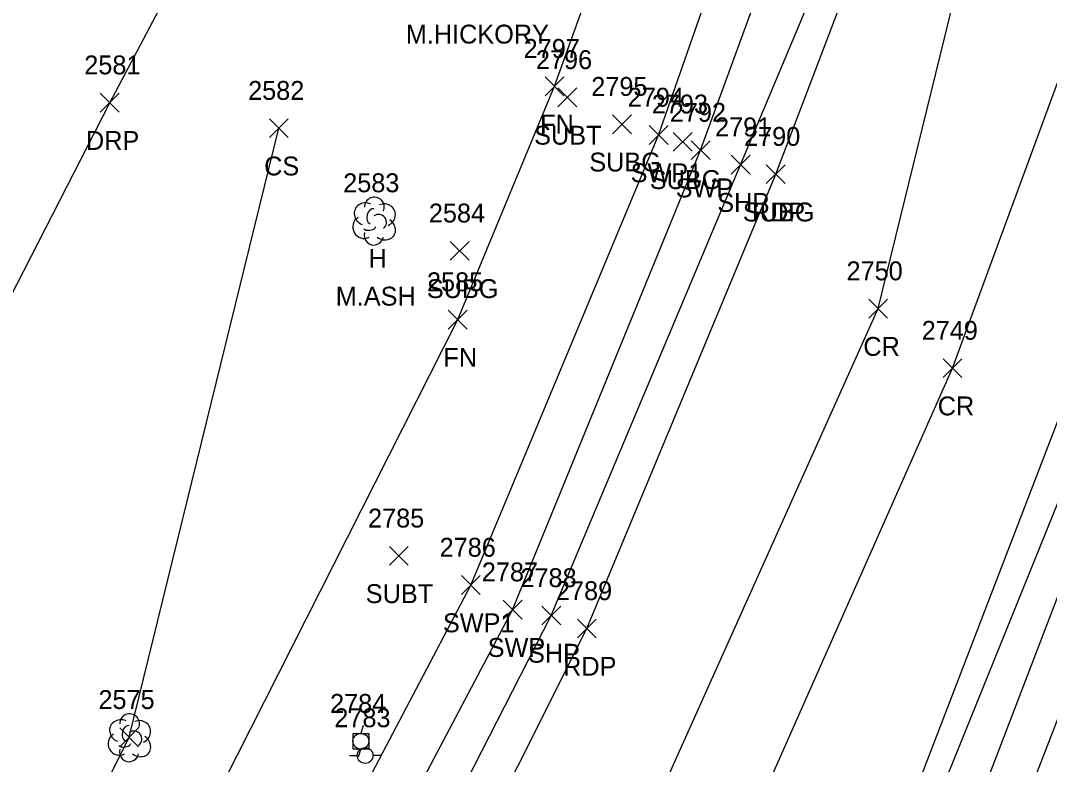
# Model space of a CAD drawing. Extents: x 1477930 to 1480780, y 774090 to 784647.
# Drawn here: x 1479402.4 to 1479511.3, y 774963.7 to 775042.4 of the extents above; entities that cross this region are included whole.
import ezdxf

# ---------------------------------------------------------------- set-up
doc = ezdxf.new("R2010")
doc.units = 0
for name, color, linetype in [('L_A', 7, 'Continuous'), ('L_C', 7, 'Continuous'), ('L_I', 7, 'Continuous'), ('L_TIC', 7, 'Continuous'), ('LELB', 7, 'Continuous'), ('LFNC', 7, 'Continuous'), ('LTD', 7, 'Continuous'), ('P_A', 7, 'Continuous'), ('P_I', 7, 'Continuous'), ('P_TIC', 7, 'Continuous'), ('PET', 7, 'Continuous'), ('PRC', 7, 'Continuous'), ('PSP', 7, 'Continuous'), ('R_A', 7, 'Continuous'), ('R_I', 7, 'Continuous'), ('R_TIC', 7, 'Continuous'), ('RDP', 7, 'Continuous'), ('RSW', 7, 'Continuous'), ('U_A', 7, 'Continuous'), ('U_I', 7, 'Continuous'), ('U_TIC', 7, 'Continuous'), ('UP', 7, 'Continuous')]:
    doc.layers.add(name, color=color, linetype=linetype)

msp = doc.modelspace()

# ---------------------------------------------------------------- linework, layer by layer
at = {"layer": 'L_TIC'}
for points in [[(1479457.93, 775034.46), (1479459.93, 775036.46)], [(1479459.93, 775034.46), (1479457.93, 775036.46)], [(1479428.74, 775030.02), (1479430.74, 775032.02)], [(1479430.74, 775030.02), (1479428.74, 775032.02)], [(1479447.69, 775009.76), (1479449.69, 775011.76)], [(1479449.69, 775009.76), (1479447.69, 775011.76)], [(1479412.9, 774965.54), (1479414.9, 774967.54)], [(1479414.9, 774965.54), (1479412.9, 774967.54)]]:
    msp.add_lwpolyline(points, dxfattribs=at)
at = {"layer": 'LELB'}
for points in [[(1479495.75, 774910.51), (1479499.97, 774927.51), (1479504.38, 774948.16), (1479520.64, 774990.18), (1479525.58, 774996.15), (1479529.8, 774996.91), (1479531.37, 775007.34), (1479547.96, 775049.91), (1479566.92, 775099.68), (1479572.67, 775121.86), (1479581.47, 775151.49), (1479585.92, 775173.63), (1479582, 775184.73)], [(1479486.95, 774912.8), (1479492.72, 774931.11), (1479499.77, 774948.95), (1479521.2, 775004.85), (1479538.58, 775052.83), (1479555.32, 775104.12), (1479560.27, 775119.97)], [(1479384.48, 774907.4), (1479413.9, 774966.54), (1479429.74, 775031.02)]]:
    msp.add_lwpolyline(points, dxfattribs=at)
at = {"layer": 'LFNC'}
msp.add_lwpolyline([(1479373.09, 774875.08), (1479392.41, 774904.48), (1479409.31, 774932.95), (1479448.69, 775010.76), (1479458.93, 775035.46), (1479472.64, 775073.43), (1479490.33, 775128.57)], dxfattribs=at)
at = {"layer": 'LTD'}
for p, q in [((1479439.82, 775021.24), (1479439.82, 775021.24)), ((1479439.82, 775021.24), (1479439.82, 775021.24)), ((1479413.9, 774966.54), (1479413.9, 774966.54)), ((1479413.9, 774966.54), (1479413.9, 774966.54))]:
    msp.add_line(p, q, dxfattribs=at)
for centre in [(1479439.86, 775022.67), (1479413.94, 774967.97)]:
    msp.add_arc(centre, 1.05, 335.5272, 180.9563, dxfattribs=at)
for centre, major_axis, ratio, start_param, end_param in [((1479439.02, 775021.91), (1.21, -0.51), 0.895232, 1.570796, 4.712389), ((1479439.61, 775021.7), (-0.208, -0.792), 0.645439, 3.141593, 6.283185), ((1479440.86, 775021.82), (-1.14, -0.48), 0.949671, 1.570796, 4.712389), ((1479438.73, 775020.53), (0.58, -1.04), 0.959034, 3.141593, 6.283185), ((1479440.32, 775021.07), (-0.5, 0.667), 0.989748, 3.141593, 6.283185), ((1479440.82, 775020.41), (-1.09, 0.79), 0.841452, 1.570796, 4.712389), ((1479439.36, 775020.49), (-0.625, -0.083), 0.423636, 0, 3.141593), ((1479439.82, 775019.74), (0.26, 1.06), 0.942809, 1.570796, 4.712389), ((1479413.11, 774967.2), (1.21, -0.51), 0.895232, 1.570796, 4.712389), ((1479413.69, 774966.99), (-0.208, -0.792), 0.645439, 3.141593, 6.283185), ((1479414.94, 774967.12), (-1.14, -0.48), 0.949671, 1.570796, 4.712389), ((1479412.81, 774965.83), (0.58, -1.04), 0.959034, 3.141593, 6.283185), ((1479414.4, 774966.37), (-0.5, 0.667), 0.989748, 3.141593, 6.283185), ((1479413.44, 774965.79), (-0.625, -0.083), 0.423636, 0, 3.141593), ((1479414.9, 774965.7), (-1.09, 0.79), 0.841452, 1.570796, 4.712389), ((1479413.9, 774965.04), (0.26, 1.06), 0.942809, 1.570796, 4.712389)]:
    msp.add_ellipse(centre, major_axis=major_axis, ratio=ratio, start_param=start_param, end_param=end_param, dxfattribs=at)
at = {"layer": 'P_TIC'}
for points in [[(1479477.64, 775026.16), (1479479.64, 775028.16)], [(1479479.64, 775026.16), (1479477.64, 775028.16)], [(1479481.36, 775025.15), (1479483.36, 775027.15)], [(1479483.36, 775025.15), (1479481.36, 775027.15)], [(1479492.21, 775010.92), (1479494.21, 775012.92)], [(1479494.21, 775010.92), (1479492.21, 775012.92)], [(1479500.08, 775004.62), (1479502.08, 775006.62)], [(1479502.08, 775004.62), (1479500.08, 775006.62)], [(1479457.59, 774978.44), (1479459.59, 774980.44)], [(1479459.59, 774978.44), (1479457.59, 774980.44)], [(1479461.36, 774977.06), (1479463.36, 774979.06)], [(1479463.36, 774977.06), (1479461.36, 774979.06)]]:
    msp.add_lwpolyline(points, dxfattribs=at)
at = {"layer": 'PET'}
for points in [[(1479231.31, 774636.06), (1479272.54, 774672.78), (1479302.99, 774702.6), (1479344.22, 774746.86), (1479373.44, 774780.01), (1479405.23, 774818.27), (1479428.23, 774848.68), (1479447.93, 774875.75), (1479460.71, 774894.51), (1479479.69, 774925.18), (1479480.31, 774927.38), (1479493.45, 774951.2), (1479514.74, 775006.53), (1479531.7, 775055.13), (1479548.14, 775106.72), (1479553.83, 775125.43), (1479564.45, 775161.29), (1479573.74, 775193.3), (1479576.58, 775204.25), (1479585.43, 775238.68), (1479593.96, 775273.34), (1479599.4, 775295.6)], [(1479168.73, 774620.31), (1479212.4, 774655.38), (1479259.7, 774697.56), (1479293.15, 774732.73), (1479318.8, 774762.89), (1479333.57, 774781.21), (1479355.81, 774805.14), (1479380.51, 774839), (1479394.88, 774859.45), (1479419.72, 774898.43), (1479440.51, 774934.48), (1479462.36, 774978.06), (1479482.36, 775026.15), (1479497.52, 775065.91), (1479509.28, 775100.79), (1479510.93, 775118.31)]]:
    msp.add_lwpolyline(points, dxfattribs=at)
at = {"layer": 'PRC'}
for points in [[(1479430.01, 774890.62), (1479468.91, 774957.83), (1479493.21, 775011.92), (1479503.06, 775052.08), (1479530.4, 775123.25), (1479541.54, 775166.06), (1479555.58, 775209.55), (1479571.78, 775263.31), (1479582.9, 775300.17)], [(1479438.76, 774885), (1479466.69, 774929.85), (1479479.06, 774955.89), (1479501.08, 775005.62), (1479520.94, 775059.64), (1479540.23, 775118.92), (1479552.22, 775163.96), (1479564.07, 775206.06), (1479578.9, 775260.88), (1479588.27, 775297.78)]]:
    msp.add_lwpolyline(points, dxfattribs=at)
at = {"layer": 'PSP'}
for points in [[(1479441.63, 774858.96), (1479460.29, 774885.01), (1479481.52, 774912.36), (1479488.61, 774932.58), (1479495.59, 774950.17), (1479517.9, 775005.3), (1479535.63, 775053.88), (1479551.95, 775105.38), (1479558.13, 775123.89), (1479568.29, 775159.47), (1479576.91, 775192.14), (1479579.19, 775198.63), (1479580.51, 775203.37), (1479590.38, 775237.67), (1479592.66, 775242.36), (1479594.67, 775243.82)], [(1479333.57, 774781.21), (1479353.18, 774806.91), (1479376.82, 774840.34), (1479390.8, 774862.22), (1479415.7, 774900.26), (1479436.53, 774936.29), (1479458.59, 774979.44), (1479478.64, 775027.16), (1479495.22, 775066.68), (1479506.41, 775101.31), (1479509.16, 775114.37), (1479508.43, 775127.01)]]:
    msp.add_lwpolyline(points, dxfattribs=at)
at = {"layer": 'R_TIC'}
for points in [[(1479410.83, 775032.72), (1479412.83, 775034.72)], [(1479412.83, 775032.72), (1479410.83, 775034.72)], [(1479468.96, 775029.3), (1479470.96, 775031.3)], [(1479470.96, 775029.3), (1479468.96, 775031.3)], [(1479473.41, 775027.7), (1479475.41, 775029.7)], [(1479475.41, 775027.7), (1479473.41, 775029.7)], [(1479449.08, 774981.66), (1479451.08, 774983.66)], [(1479451.08, 774981.66), (1479449.08, 774983.66)], [(1479453.5, 774979.05), (1479455.5, 774981.05)], [(1479455.5, 774979.05), (1479453.5, 774981.05)]]:
    msp.add_lwpolyline(points, dxfattribs=at)
at = {"layer": 'RDP'}
msp.add_lwpolyline([(1479341.82, 774898.99), (1479353.71, 774920.58), (1479370.62, 774953.72), (1479387.55, 774986.35), (1479411.83, 775033.72), (1479422.89, 775054.64)], dxfattribs=at)
at = {"layer": 'RSW'}
for points in [[(1479274.17, 774731.39), (1479308.42, 774770.17), (1479343.53, 774813.46), (1479368.77, 774847.04), (1479380.89, 774863.8), (1479383.37, 774867.44), (1479386.24, 774871.51), (1479407.11, 774905.13), (1479428.53, 774941.71), (1479450.08, 774982.66), (1479469.96, 775030.3), (1479484.01, 775070.5), (1479497.13, 775105.7)], [(1479277.58, 774728.25), (1479312.53, 774767.11), (1479348.01, 774809.99), (1479373.39, 774844.03), (1479387.54, 774864.22), (1479390.19, 774868.27), (1479411.38, 774902.61), (1479432.83, 774938.99), (1479454.5, 774980.05), (1479474.41, 775028.7), (1479489.03, 775068.75), (1479501.66, 775103.93)]]:
    msp.add_lwpolyline(points, dxfattribs=at)
at = {"layer": 'U_TIC'}
for points in [[(1479459.29, 775033.28), (1479461.29, 775035.28)], [(1479461.29, 775033.28), (1479459.29, 775035.28)], [(1479465.09, 775030.44), (1479467.09, 775032.44)], [(1479467.09, 775030.44), (1479465.09, 775032.44)], [(1479471.5, 775028.58), (1479473.5, 775030.58)], [(1479473.5, 775028.58), (1479471.5, 775030.58)], [(1479481.36, 775025.15), (1479483.36, 775027.15)], [(1479483.36, 775025.15), (1479481.36, 775027.15)], [(1479447.89, 775017.04), (1479449.89, 775019.04)], [(1479449.89, 775017.04), (1479447.89, 775019.04)], [(1479441.45, 774984.75), (1479443.45, 774986.75)], [(1479443.45, 774984.75), (1479441.45, 774986.75)]]:
    msp.add_lwpolyline(points, dxfattribs=at)
at = {"layer": 'UP'}
for p, q in [((1479438.68, 774967.8), (1479438.43, 774966.96)), ((1479437.6, 774965.3), (1479437.6, 774966.96)), ((1479437.6, 774966.96), (1479439.26, 774966.96)), ((1479439.26, 774966.96), (1479439.26, 774965.3)), ((1479438.43, 774966.13), (1479438.43, 774966.13)), ((1479437.22, 774964.61), (1479438.05, 774964.61)), ((1479439.26, 774965.3), (1479437.6, 774965.3)), ((1479438.18, 774964.46), (1479438.43, 774965.3)), ((1479438.88, 774964.61), (1479438.88, 774964.61)), ((1479440.55, 774964.61), (1479439.71, 774964.61)), ((1479439.71, 774964.61), (1479439.71, 774964.61)), ((1479440.55, 774964.61), (1479440.55, 774964.61))]:
    msp.add_line(p, q, dxfattribs=at)
for centre in [(1479438.43, 774966.13), (1479438.88, 774964.61)]:
    msp.add_circle(centre, 0.833, dxfattribs=at)

# ---------------------------------------------------------------- texts
at = {"layer": 'L_A'}
for s, p in [('FN', (1479457.41, 775030.46)), ('CS', (1479428.19, 775026.02)), ('H', (1479439.25, 775016.24)), ('FN', (1479447.17, 775005.76))]:
    msp.add_text(s, height=2, dxfattribs=at).set_placement(p)
at = {"layer": 'L_C'}
for s, p in [('M.HICKORY', (1479443.19, 775039.98)), ('M.ASH', (1479435.77, 775012.24))]:
    msp.add_text(s, height=2, dxfattribs=at).set_placement(p)
at = {"layer": 'L_I'}
for s, p in [('2797', (1479455.67, 775038.46)), ('2582', (1479426.49, 775034.02)), ('2583', (1479436.56, 775024.24)), ('2585', (1479445.43, 775013.76)), ('2575', (1479410.64, 774969.54)), ('2575', (1479410.64, 774969.54))]:
    msp.add_text(s, height=2, dxfattribs=at).set_placement(p)
at = {"layer": 'P_A'}
for s, p in [('SHP', (1479476.17, 775022.16)), ('RDP', (1479479.84, 775021.15)), ('CR', (1479491.64, 775006.92)), ('CR', (1479499.52, 775000.62)), ('SHP', (1479456.13, 774974.44)), ('RDP', (1479459.85, 774973.06))]:
    msp.add_text(s, height=2, dxfattribs=at).set_placement(p)
at = {"layer": 'P_I'}
for s, p in [('2791', (1479475.94, 775030.16)), ('2790', (1479479.01, 775029.15)), ('2750', (1479489.86, 775014.92)), ('2749', (1479497.82, 775008.62)), ('2788', (1479455.33, 774982.44)), ('2789', (1479459.09, 774981.06))]:
    msp.add_text(s, height=2, dxfattribs=at).set_placement(p)
at = {"layer": 'R_A'}
for s, p in [('DRP', (1479409.32, 775028.72)), ('SWP1', (1479467, 775025.3)), ('SWP', (1479471.77, 775023.7)), ('SWP1', (1479447.12, 774977.66)), ('SWP', (1479451.86, 774975.05))]:
    msp.add_text(s, height=2, dxfattribs=at).set_placement(p)
at = {"layer": 'R_I'}
for s, p in [('2581', (1479409.14, 775036.72)), ('2794', (1479466.7, 775033.3)), ('2792', (1479471.15, 775031.7)), ('2786', (1479446.77, 774985.66)), ('2787', (1479451.24, 774983.05))]:
    msp.add_text(s, height=2, dxfattribs=at).set_placement(p)
at = {"layer": 'U_A'}
for s, p in [('SUBT', (1479456.78, 775029.28)), ('SUBG', (1479462.62, 775026.44)), ('SUBG', (1479469.02, 775024.58)), ('SUBG', (1479478.88, 775021.15)), ('SUBG', (1479445.42, 775013.04)), ('SUBT', (1479438.95, 774980.75))]:
    msp.add_text(s, height=2, dxfattribs=at).set_placement(p)
at = {"layer": 'U_I'}
for s, p in [('2796', (1479456.97, 775037.28)), ('2795', (1479462.83, 775034.44)), ('2793', (1479469.24, 775032.58)), ('2790', (1479479.01, 775029.15)), ('2584', (1479445.63, 775021.04)), ('2785', (1479439.19, 774988.75)), ('2784', (1479435.17, 774969.13)), ('2783', (1479435.62, 774967.61))]:
    msp.add_text(s, height=2, dxfattribs=at).set_placement(p)

doc.saveas('drawing.dxf')
